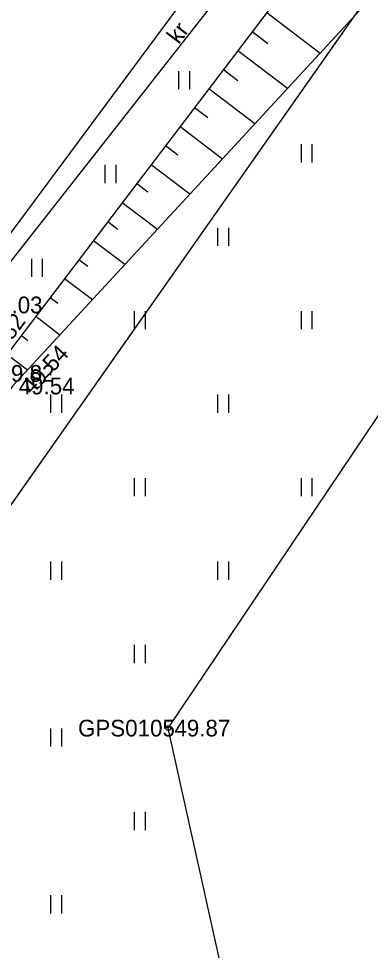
# Model space of a CAD drawing. Extents: x 563121 to 567545, y 6570841 to 6581299.
# Drawn here: x 565807.43 to 565822.17, y 6571805.07 to 6571844.15 of the extents above; entities that cross this region are included whole.
import ezdxf

# ---------------------------------------------------------------- set-up
doc = ezdxf.new("R2010")
doc.units = 0
for name, color, linetype in [('HALJASTUS', 7, 'Continuous'), ('KORGUS-EH2000', 7, 'Continuous'), ('MOOTKORG-EH2000', 7, 'Continuous'), ('MOOTMPUNKT', 7, 'Continuous'), ('MOOTNR', 7, 'Continuous'), ('MOOTPIIR', 7, 'Continuous'), ('PIIR', 7, 'Continuous'), ('RELJEEF', 7, 'Continuous'), ('TEE', 7, 'Continuous')]:
    doc.layers.add(name, color=color, linetype=linetype)

msp = doc.modelspace()

# ---------------------------------------------------------------- linework, layer by layer
at = {"layer": 'HALJASTUS'}
for p, q in [((565814.134, 6571841.947), (565814.134, 6571841.186)), ((565814.589, 6571841.947), (565814.589, 6571841.186)), ((565819.272, 6571838.881), (565819.272, 6571838.119)), ((565819.728, 6571838.881), (565819.728, 6571838.119)), ((565811.05, 6571838.011), (565811.05, 6571837.25)), ((565811.506, 6571838.011), (565811.506, 6571837.25)), ((565815.772, 6571835.381), (565815.772, 6571834.619)), ((565816.228, 6571835.381), (565816.228, 6571834.619)), ((565807.967, 6571834.076), (565807.967, 6571833.314)), ((565808.422, 6571834.076), (565808.422, 6571833.314)), ((565812.272, 6571831.881), (565812.272, 6571831.119)), ((565812.728, 6571831.881), (565812.728, 6571831.119)), ((565819.272, 6571831.881), (565819.272, 6571831.119)), ((565819.728, 6571831.881), (565819.728, 6571831.119)), ((565808.772, 6571828.381), (565808.772, 6571827.619)), ((565809.228, 6571828.381), (565809.228, 6571827.619)), ((565815.772, 6571828.381), (565815.772, 6571827.619)), ((565816.228, 6571828.381), (565816.228, 6571827.619)), ((565812.272, 6571824.881), (565812.272, 6571824.119)), ((565812.728, 6571824.881), (565812.728, 6571824.119)), ((565819.272, 6571824.881), (565819.272, 6571824.119)), ((565819.728, 6571824.881), (565819.728, 6571824.119)), ((565808.772, 6571821.381), (565808.772, 6571820.619)), ((565809.228, 6571821.381), (565809.228, 6571820.619)), ((565815.772, 6571821.381), (565815.772, 6571820.619)), ((565816.228, 6571821.381), (565816.228, 6571820.619)), ((565812.272, 6571817.881), (565812.272, 6571817.119)), ((565812.728, 6571817.881), (565812.728, 6571817.119)), ((565808.772, 6571814.381), (565808.772, 6571813.619)), ((565809.228, 6571814.381), (565809.228, 6571813.619)), ((565812.272, 6571810.881), (565812.272, 6571810.119)), ((565812.728, 6571810.881), (565812.728, 6571810.119)), ((565808.772, 6571807.381), (565808.772, 6571806.619)), ((565809.228, 6571807.381), (565809.228, 6571806.619))]:
    msp.add_line(p, q, dxfattribs=at)
at = {"layer": 'KORGUS-EH2000'}
msp.add_circle((565813.701, 6571814.393), 0.1, dxfattribs=at)
at = {"layer": 'MOOTMPUNKT'}
msp.add_circle((565813.701, 6571814.393), 0.1, dxfattribs=at)
at = {"layer": 'MOOTPIIR'}
msp.add_lwpolyline([(565818.889, 6571791.023), (565813.701, 6571814.393), (565829.693, 6571838.184)], dxfattribs=at)
at = {"layer": 'PIIR'}
msp.add_lwpolyline([(566138.88, 6572289.1), (566071.95, 6572189.53), (566056.92, 6572168.48), (566043.44, 6572149.59), (566020.47, 6572117.41), (565845.87, 6571876.56), (565833.02, 6571860.66), (565803.59, 6571818.77), (565766.84, 6571778.8), (565712.27, 6571733.72), (565636.36, 6571689.97), (565561.65, 6571658.97), (565400, 6571600), (565315, 6571572), (565230, 6571552), (564980, 6571552), (564921.56, 6571543.26)], dxfattribs=at)
msp.add_lwpolyline([(565833.02, 6571860.66), (565851.06, 6571859.65), (565901.01, 6571846.54), (565960.44, 6571833.78), (565973.49, 6571828.72), (566023.53, 6571796.39), (566089.86, 6571753.57), (566110.96, 6571742.32), (566147.53, 6571725.81), (566160.83, 6571717.7), (565835.49, 6571610.61), (565803.59, 6571818.77)], close=True, dxfattribs=at)
at = {"layer": 'RELJEEF'}
for p, q in [((565817.828, 6571844.401), (565820.064, 6571842.701)), ((565817.223, 6571843.604), (565817.871, 6571843.112)), ((565816.618, 6571842.808), (565818.701, 6571841.225)), ((565816.013, 6571842.012), (565816.615, 6571841.555)), ((565815.408, 6571841.216), (565817.338, 6571839.749)), ((565814.803, 6571840.42), (565815.359, 6571839.997)), ((565814.198, 6571839.624), (565815.975, 6571838.272)), ((565813.592, 6571838.828), (565814.103, 6571838.44)), ((565812.987, 6571838.032), (565814.612, 6571836.796)), ((565812.382, 6571837.235), (565812.847, 6571836.882)), ((565811.777, 6571836.439), (565813.249, 6571835.32)), ((565811.172, 6571835.643), (565811.591, 6571835.325)), ((565810.567, 6571834.847), (565811.887, 6571833.844)), ((565809.961, 6571834.051), (565810.335, 6571833.767)), ((565809.356, 6571833.255), (565810.524, 6571832.368)), ((565808.751, 6571832.459), (565809.078, 6571832.21)), ((565808.146, 6571831.663), (565809.161, 6571830.892)), ((565807.541, 6571830.867), (565807.822, 6571830.653)), ((565806.936, 6571830.07), (565807.798, 6571829.415))]:
    msp.add_line(p, q, dxfattribs=at)
for points in [[(565844.04, 6571859.801), (565839.307, 6571861.411), (565835.818, 6571862.396), (565833.848, 6571861.926), (565831.495, 6571861.254), (565830.033, 6571859.153), (565819.486, 6571846.581), (565806.328, 6571829.271), (565803.644, 6571823.76)], [(565830.061, 6571854.393), (565821.897, 6571844.686), (565807.174, 6571828.74), (565803.644, 6571823.76)]]:
    msp.add_lwpolyline(points, dxfattribs=at)
at = {"layer": 'TEE'}
for points in [[(565839.194, 6571863.521), (565833.439, 6571863.766), (565828.407, 6571862.073), (565825.907, 6571860.285), (565817.092, 6571848.675), (565804.137, 6571831.188), (565797.898, 6571823.166), (565798.048, 6571821.994), (565800.139, 6571818.615), (565801.078, 6571813.504), (565797.777, 6571812.08), (565794.654, 6571813.34), (565791.141, 6571814.563), (565789.374, 6571812.429)], [(565833.439, 6571863.766), (565828.71, 6571861.712), (565827.373, 6571860.217), (565817.957, 6571847.828), (565804.535, 6571830.717), (565801.583, 6571826.805), (565800.955, 6571825.15), (565801.025, 6571821.866), (565801.467, 6571818.976), (565802.633, 6571814.638), (565802.718, 6571813.36), (565804.674, 6571805.685), (565807.231, 6571788.975), (565811.315, 6571764.792), (565815.474, 6571739.551), (565820.53, 6571709.209), (565821.038, 6571705.752), (565823.803, 6571687.466)]]:
    msp.add_lwpolyline(points, dxfattribs=at)

# ---------------------------------------------------------------- texts
at = {"layer": 'KORGUS-EH2000'}
for s, rotation, p in [(' 49.82', 52.7605, (565806.188, 6571829.377)), (' 49.54', 47.2832, (565807.817, 6571828.146))]:
    msp.add_text(s, height=0.7, rotation=rotation, dxfattribs=at).set_placement(p)
msp.add_text(' 49.87', height=0.7, dxfattribs=at).set_placement((565813.701, 6571814.043))
at = {"layer": 'MOOTKORG-EH2000'}
for s, p in [(' 50.03', (565805.83, 6571831.79)), (' 49.82', (565806.328, 6571828.921)), (' 49.54', (565807.174, 6571828.39)), (' 49.87', (565813.701, 6571814.043))]:
    msp.add_text(s, height=0.7, dxfattribs=at).set_placement(p)
at = {"layer": 'MOOTNR'}
msp.add_text('GPS0105 ', height=0.7, dxfattribs=at).set_placement((565809.921, 6571814.043))
at = {"layer": 'TEE'}
msp.add_text('kr', height=0.7, rotation=52.9828, dxfattribs=at).set_placement((565814.143, 6571843.041))

doc.saveas('drawing.dxf')
